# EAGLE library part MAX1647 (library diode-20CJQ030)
Maxim's MAX1647 Chemistry-Independent Battery Chargers General Description: The MAX1647/MAX1648 provide the power control necessary to charge batteries of any chemistry. In the MAX1647, all charging functions are controlled through the Intel System Management Bus (SMBus?) interface. The SMBus 2-wire serial interface sets the charge voltage and current, and provides thermal status information. The MAX1647 functions as a level 2 charger, compliant with the Duracell/Intel Smart Battery Charger Specification. The MAX1648 omits the SMBus serial interface, and instead sets the charge voltage and current proportional to the voltage applied to external control pins. In addition to the feature set required for a level 2 charger, the MAX1647 generates interrupts to signal the host when power is applied to the charger or a battery is installed or removed. Additional status bits allow the host to check whether the charger has enough input voltage, and whether the voltage on or current into the battery is being regulated. This allows the host to determine when lithiumion batteries have completed charge without interrogating the battery. The MAX1647 is available in a 20-pin SSOP with a 2mm profile height. The MAX1648 is available in a 16-pin SO package. Features: Charges Any Battery Chemistry: Li-Ion, NiCd, NiMH, Lead Acid, etc. Intel SMBus 2-Wire Serial Interface (MAX1647) Intel/Duracell Level 2 Smart Battery Compliant (MAX1647) 4A, 2A, or 1A Maximum Battery-Charge Current 11-Bit Control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
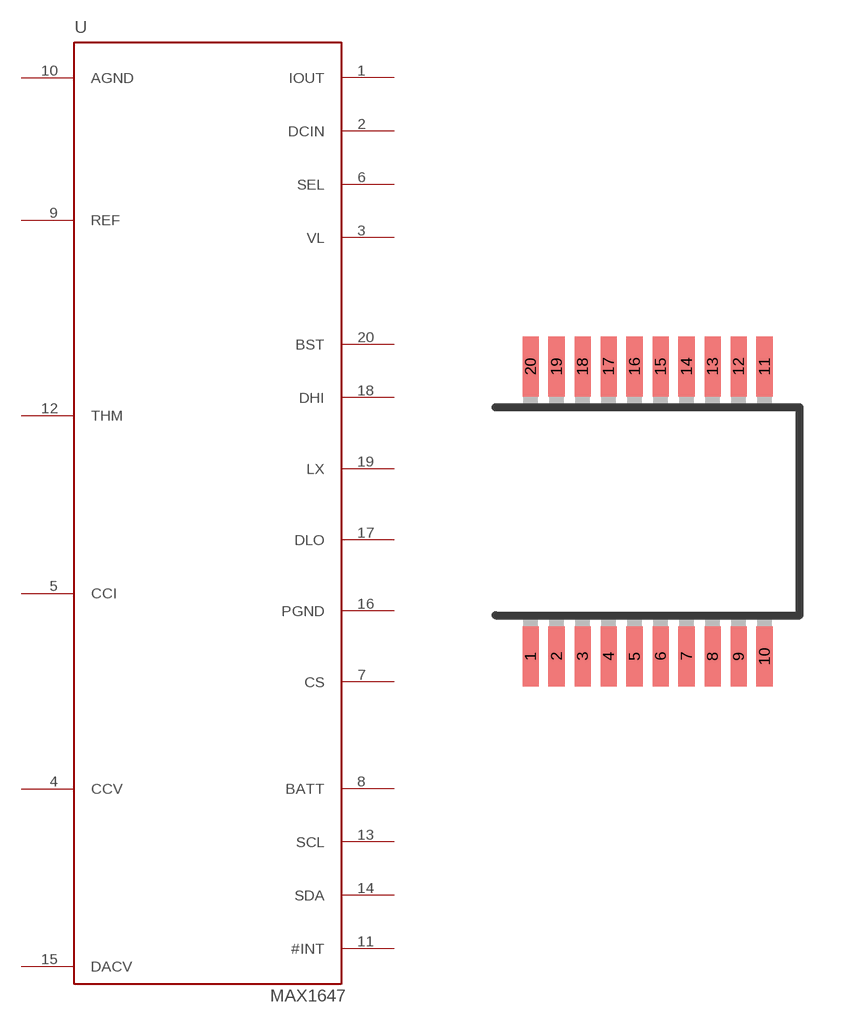
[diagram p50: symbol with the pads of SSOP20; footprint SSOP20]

Designator prefix U

## MAX1647  [SSOP20]
1  IOUT
2  DCIN
3  VL
4  CCV
5  CCI
6  SEL
7  CS
8  BATT
9  REF
10  AGND
11  #INT
12  THM
13  SCL
14  SDA
15  DACV
16  PGND
17  DLO
18  DHI
19  LX
20  BST

## Footprint SSOP20 (pad centres in mm)
Shrink Small Outline Package package type SS
smd 0.4 x 1.5: 1 -2.925,-3.625; 2 -2.275,-3.625; 3 -1.625,-3.625; 4 -0.975,-3.625; 5 -0.325,-3.625; 6 0.325,-3.625; 7 0.975,-3.625; 8 1.625,-3.625; 9 2.275,-3.625; 10 2.925,-3.625; 11 2.925,3.625; 12 2.275,3.625; 13 1.625,3.625; 14 0.975,3.625; 15 0.325,3.625; 16 -0.325,3.625; 17 -0.975,3.625; 18 -1.625,3.625; 19 -2.275,3.625; 20 -2.925,3.625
